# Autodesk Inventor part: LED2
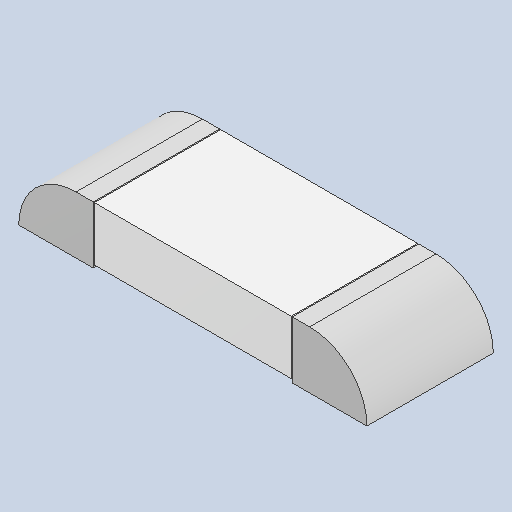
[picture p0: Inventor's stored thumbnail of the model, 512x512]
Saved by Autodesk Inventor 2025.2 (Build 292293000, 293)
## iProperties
Created: 2025-04
Part Number: LED2
Material: Generic
Description: PART-LED2-DESC
Document SubType Name: Modeling
Designer: BennF
Density: 1 g/cm^3
Appearance: Default
Author: BennF
Revision Number: NONE
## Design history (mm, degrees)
feature "pin"
feature "Solid"
body "Solid1"
body "Solid2"
